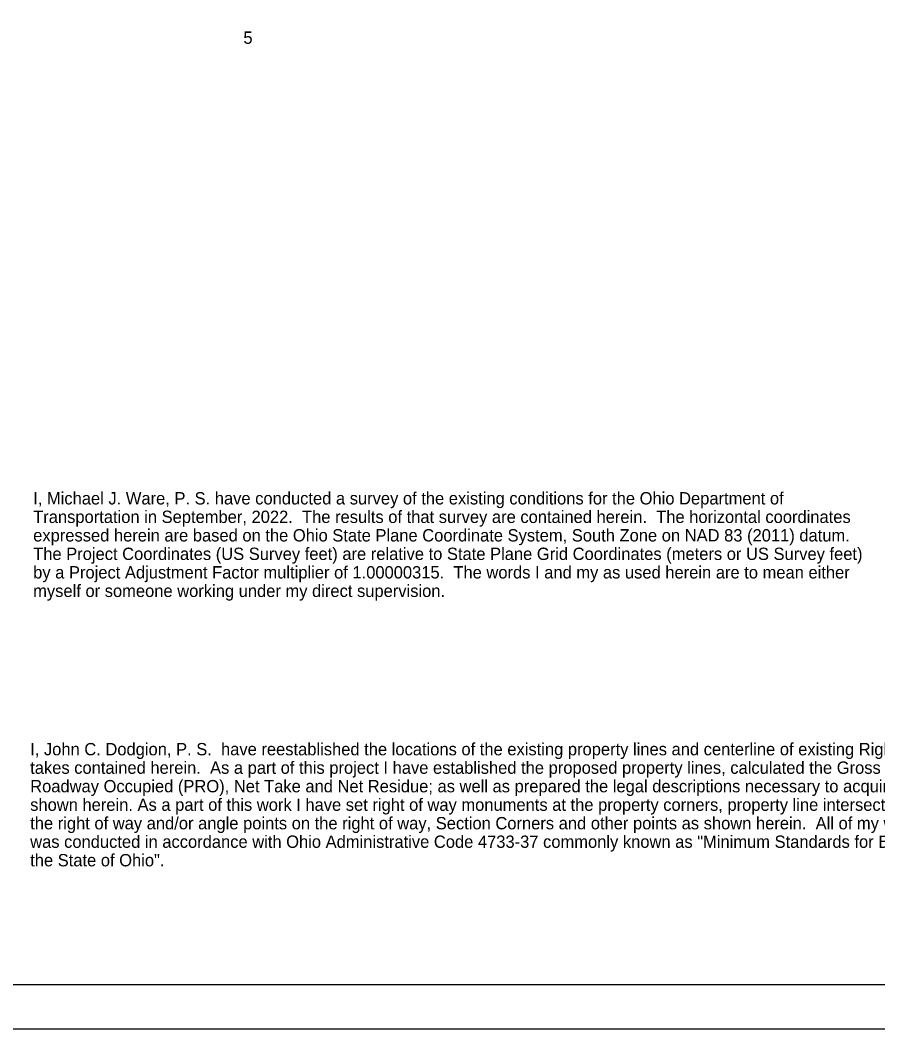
# Model space of a CAD drawing. Extents: x 0 to 34, y 0 to 22.
# Drawn here: x 15.51 to 25.23, y 0 to 11.45 of the extents above; entities that cross this region are included whole.
import ezdxf

# ---------------------------------------------------------------- set-up
doc = ezdxf.new("R2010")
doc.units = 0
for name, color, linetype in [('SH_Border', 7, 'Continuous'), ('SH_Cut_Line', 7, 'Continuous'), ('SH_Data', 7, 'Continuous'), ('SH_Text', 7, 'Continuous')]:
    doc.layers.add(name, color=color, linetype=linetype)

msp = doc.modelspace()

# ---------------------------------------------------------------- linework, layer by layer
at = {"layer": 'SH_Border'}
msp.add_lwpolyline([(1.5, 21.5), (33.5, 21.5), (33.5, 0.5), (1.5, 0.5)], close=True, dxfattribs=at)
at = {"layer": 'SH_Cut_Line'}
msp.add_lwpolyline([(0, 0), (34, 0), (34, 22), (0, 22)], close=True, dxfattribs=at)

# ---------------------------------------------------------------- texts
at = {"layer": 'SH_Data'}
msp.add_text('5', height=0.14, dxfattribs=at).set_placement((18.038, 11.179))
at = {"layer": 'SH_Text'}
for s, p in [('I, Michael J. Ware, P. S. have conducted a survey of the existing conditions for the Ohio Department of', (15.654, 5.951)), ('Transportation in September, 2022.  The results of that survey are contained herein.  The horizontal coordinates', (15.654, 5.741)), ('expressed herein are based on the Ohio State Plane Coordinate System, South Zone on NAD 83 (2011) datum.', (15.654, 5.531)), ('The Project Coordinates (US Survey feet) are relative to State Plane Grid Coordinates (meters or US Survey feet)', (15.654, 5.321)), ('by a Project Adjustment Factor multiplier of 1.00000315.  The words I and my as used herein are to mean either', (15.654, 5.111)), ('myself or someone working under my direct supervision.', (15.654, 4.901)), ('I, John C. Dodgion, P. S.  have reestablished the locations of the existing property lines and centerline of existing Right of Way for property', (15.62, 3.104)), ('takes contained herein.  As a part of this project I have established the proposed property lines, calculated the Gross Take, Present', (15.62, 2.894)), ('Roadway Occupied (PRO), Net Take and Net Residue; as well as prepared the legal descriptions necessary to acquire these parcels as', (15.62, 2.684)), ('shown herein. As a part of this work I have set right of way monuments at the property corners, property line intersections, points along', (15.62, 2.474)), ('the right of way and/or angle points on the right of way, Section Corners and other points as shown herein.  All of my work contained herein', (15.62, 2.264)), ('was conducted in accordance with Ohio Administrative Code 4733-37 commonly known as "Minimum Standards for Boundary Surveys in', (15.62, 2.054)), ('the State of Ohio".', (15.62, 1.844))]:
    msp.add_text(s, height=0.14, dxfattribs=at).set_placement(p)

doc.saveas('drawing.dxf')
